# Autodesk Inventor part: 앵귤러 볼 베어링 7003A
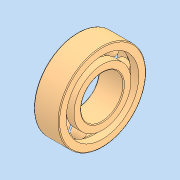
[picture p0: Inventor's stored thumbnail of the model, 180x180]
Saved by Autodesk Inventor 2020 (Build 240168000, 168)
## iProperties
Created: 2024-11
Part Number: 앵귤러 볼 베어링 7003A
Material: 강철, 연강
Description: 앵귤러 콘택트 볼 베어링
Document SubType Name: Modeling
Designer: 1강의실14
Density: 7.85 g/cm^3
Appearance: 기본값
Author: jhkim
Sending System: Autodesk Inventor 2025
Preprocessor: ST-DEVELOPER v20
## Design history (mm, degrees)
node "앵귤러 볼 베어링 7003A1"
node "솔리드1"
node "솔리드2"
node "솔리드3"
node "솔리드4"
node "솔리드5"
node "솔리드6"
node "솔리드7"
node "솔리드8"
node "솔리드9"
node "솔리드10"
node "솔리드11"
body "Solid1"
node "Solid1:1"
node "Solid1:2"
node "Solid1:3"
node "Solid1:4"
node "Solid1:5"
node "Solid1:6"
node "Solid1:7"
node "Solid1:8"
node "Solid1:9"
node "Solid1:10"
